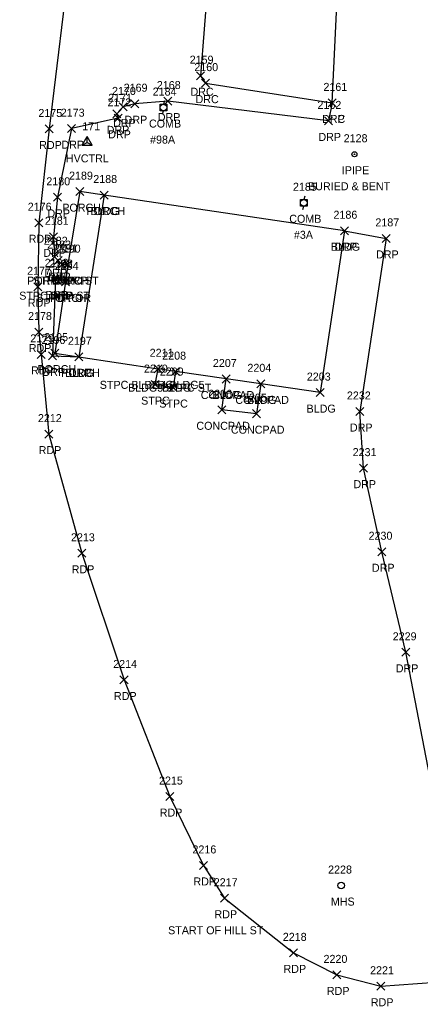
# Model space of a CAD drawing. Extents: x 1767353 to 1772625, y 740790 to 747702.
# Drawn here: x 1770037.8 to 1770137.8, y 741104.5 to 741351 of the extents above; entities that cross this region are included whole.
import ezdxf

# ---------------------------------------------------------------- set-up
doc = ezdxf.new("R2010")
doc.units = 0
for name, color, linetype in [('C_A', 7, 'Continuous'), ('C_I', 7, 'Continuous'), ('CPSM', 7, 'Continuous'), ('L_A', 7, 'Continuous'), ('L_I', 7, 'Continuous'), ('L_TIC', 7, 'Continuous'), ('LBC', 7, 'Continuous'), ('LBF', 7, 'Continuous'), ('LS', 7, 'Continuous'), ('M_A', 7, 'Continuous'), ('M_C', 7, 'Continuous'), ('M_I', 7, 'Continuous'), ('MPIP', 7, 'Continuous'), ('P_A', 7, 'Continuous'), ('P_C', 7, 'Continuous'), ('P_I', 7, 'Continuous'), ('P_TIC', 7, 'Continuous'), ('PET', 7, 'Continuous'), ('R_A', 7, 'Continuous'), ('R_I', 7, 'Continuous'), ('R_TIC', 7, 'Continuous'), ('RDP', 7, 'Continuous'), ('U_A', 7, 'Continuous'), ('U_C', 7, 'Continuous'), ('U_I', 7, 'Continuous'), ('UP', 7, 'Continuous'), ('USMH', 7, 'Continuous')]:
    doc.layers.add(name, color=color, linetype=linetype)

msp = doc.modelspace()

# ---------------------------------------------------------------- linework, layer by layer
at = {"layer": 'CPSM'}
for p, q in [((1770053.4, 741319.61), (1770054.65, 741321.77)), ((1770055.9, 741319.61), (1770054.65, 741321.77)), ((1770054.65, 741320.33), (1770054.65, 741321.77)), ((1770053.4, 741319.61), (1770054.65, 741320.33)), ((1770053.4, 741319.61), (1770055.9, 741319.61)), ((1770054.65, 741320.33), (1770054.65, 741320.33)), ((1770054.65, 741320.33), (1770055.9, 741319.61))]:
    msp.add_line(p, q, dxfattribs=at)
at = {"layer": 'L_TIC'}
for points in [[(1770051.83, 741307.02), (1770053.83, 741309.02)], [(1770053.83, 741307.02), (1770051.83, 741309.02)], [(1770057.87, 741306.17), (1770059.87, 741308.17)], [(1770059.87, 741306.17), (1770057.87, 741308.17)], [(1770057.87, 741306.17), (1770059.87, 741308.17)], [(1770059.87, 741306.17), (1770057.87, 741308.17)], [(1770117.9, 741297.25), (1770119.9, 741299.25)], [(1770119.9, 741297.25), (1770117.9, 741299.25)], [(1770117.9, 741297.25), (1770119.9, 741299.25)], [(1770119.9, 741297.25), (1770117.9, 741299.25)], [(1770047.43, 741288.82), (1770049.43, 741290.82)], [(1770049.43, 741288.82), (1770047.43, 741290.82)], [(1770048.84, 741288.78), (1770050.84, 741290.78)], [(1770050.84, 741288.78), (1770048.84, 741290.78)], [(1770048.84, 741288.78), (1770050.84, 741290.78)], [(1770050.84, 741288.78), (1770048.84, 741290.78)], [(1770046.83, 741285.03), (1770048.83, 741287.03)], [(1770048.83, 741285.03), (1770046.83, 741287.03)], [(1770048.26, 741284.47), (1770050.26, 741286.47)], [(1770050.26, 741284.47), (1770048.26, 741286.47)], [(1770048.26, 741284.47), (1770050.26, 741286.47)], [(1770050.26, 741284.47), (1770048.26, 741286.47)], [(1770045.62, 741266.69), (1770047.62, 741268.69)], [(1770047.62, 741266.69), (1770045.62, 741268.69)], [(1770051.54, 741265.76), (1770053.54, 741267.76)], [(1770053.54, 741265.76), (1770051.54, 741267.76)], [(1770051.54, 741265.76), (1770053.54, 741267.76)], [(1770053.54, 741265.76), (1770051.54, 741267.76)], [(1770071.38, 741262.76), (1770073.38, 741264.76)], [(1770073.38, 741262.76), (1770071.38, 741264.76)], [(1770071.38, 741262.76), (1770073.38, 741264.76)], [(1770073.38, 741262.76), (1770071.38, 741264.76)], [(1770071.38, 741262.76), (1770073.38, 741264.76)], [(1770073.38, 741262.76), (1770071.38, 741264.76)], [(1770075.74, 741262.06), (1770077.74, 741264.06)], [(1770077.74, 741262.06), (1770075.74, 741264.06)], [(1770075.74, 741262.06), (1770077.74, 741264.06)], [(1770077.74, 741262.06), (1770075.74, 741264.06)], [(1770088.38, 741260.22), (1770090.38, 741262.22)], [(1770090.38, 741260.22), (1770088.38, 741262.22)], [(1770088.38, 741260.22), (1770090.38, 741262.22)], [(1770090.38, 741260.22), (1770088.38, 741262.22)], [(1770070.61, 741258.82), (1770072.61, 741260.82)], [(1770072.61, 741258.82), (1770070.61, 741260.82)], [(1770075.15, 741258.08), (1770077.15, 741260.08)], [(1770077.15, 741258.08), (1770075.15, 741260.08)], [(1770097, 741259.01), (1770099, 741261.01)], [(1770099, 741259.01), (1770097, 741261.01)], [(1770097, 741259.01), (1770099, 741261.01)], [(1770099, 741259.01), (1770097, 741261.01)], [(1770111.84, 741256.82), (1770113.84, 741258.82)], [(1770113.84, 741256.82), (1770111.84, 741258.82)], [(1770087.27, 741252.53), (1770089.27, 741254.53)], [(1770089.27, 741252.53), (1770087.27, 741254.53)], [(1770095.9, 741251.56), (1770097.9, 741253.56)], [(1770097.9, 741251.56), (1770095.9, 741253.56)]]:
    msp.add_lwpolyline(points, dxfattribs=at)
at = {"layer": 'LBC'}
for points in [[(1770118.9, 741298.25), (1770058.87, 741307.17), (1770052.54, 741266.76), (1770072.38, 741263.76)], [(1770118.9, 741298.25), (1770112.84, 741257.82), (1770098, 741260.01), (1770089.38, 741261.22), (1770076.74, 741263.06), (1770072.38, 741263.76)]]:
    msp.add_lwpolyline(points, dxfattribs=at)
at = {"layer": 'LBF'}
for points in [[(1770058.87, 741307.17), (1770052.83, 741308.02), (1770049.84, 741289.78), (1770049.26, 741285.47), (1770046.62, 741267.69), (1770052.54, 741266.76)], [(1770049.84, 741289.78), (1770048.43, 741289.82), (1770047.83, 741286.03), (1770049.26, 741285.47)], [(1770076.74, 741263.06), (1770076.15, 741259.08), (1770071.61, 741259.82), (1770072.38, 741263.76)]]:
    msp.add_lwpolyline(points, dxfattribs=at)
at = {"layer": 'LS'}
msp.add_lwpolyline([(1770098, 741260.01), (1770096.9, 741252.56), (1770088.27, 741253.53), (1770089.38, 741261.22)], dxfattribs=at)
at = {"layer": 'MPIP'}
for radius in [0.625, 0.0833]:
    msp.add_circle((1770121.39, 741317.36), radius, dxfattribs=at)
at = {"layer": 'P_TIC'}
for points in [[(1770044.18, 741322.67), (1770046.18, 741324.67)], [(1770046.18, 741322.67), (1770044.18, 741324.67)], [(1770041.56, 741299.25), (1770043.56, 741301.25)], [(1770043.56, 741299.25), (1770041.56, 741301.25)], [(1770041.35, 741283.25), (1770043.35, 741285.25)], [(1770043.35, 741283.25), (1770041.35, 741285.25)], [(1770041.59, 741271.95), (1770043.59, 741273.95)], [(1770043.59, 741271.95), (1770041.59, 741273.95)], [(1770042.15, 741266.37), (1770044.15, 741268.37)], [(1770044.15, 741266.37), (1770042.15, 741268.37)], [(1770044.05, 741246.45), (1770046.05, 741248.45)], [(1770046.05, 741246.45), (1770044.05, 741248.45)], [(1770052.3, 741216.68), (1770054.3, 741218.68)], [(1770054.3, 741216.68), (1770052.3, 741218.68)], [(1770062.85, 741185.04), (1770064.85, 741187.04)], [(1770064.85, 741185.04), (1770062.85, 741187.04)], [(1770074.28, 741155.92), (1770076.28, 741157.92)], [(1770076.28, 741155.92), (1770074.28, 741157.92)], [(1770082.69, 741138.71), (1770084.69, 741140.71)], [(1770084.69, 741138.71), (1770082.69, 741140.71)], [(1770087.95, 741130.52), (1770089.95, 741132.52)], [(1770089.95, 741130.52), (1770087.95, 741132.52)], [(1770105.19, 741116.88), (1770107.19, 741118.88)], [(1770107.19, 741116.88), (1770105.19, 741118.88)], [(1770116.02, 741111.37), (1770118.02, 741113.37)], [(1770118.02, 741111.37), (1770116.02, 741113.37)], [(1770126.99, 741108.54), (1770128.99, 741110.54)], [(1770128.99, 741108.54), (1770126.99, 741110.54)]]:
    msp.add_lwpolyline(points, dxfattribs=at)
at = {"layer": 'PET'}
msp.add_lwpolyline([(1770050.58, 741368.28), (1770045.18, 741323.67), (1770042.56, 741300.25), (1770042.35, 741284.25), (1770042.59, 741272.95), (1770043.15, 741267.37), (1770045.05, 741247.45), (1770053.3, 741217.68), (1770063.85, 741186.04), (1770075.28, 741156.92), (1770083.69, 741139.71), (1770088.95, 741131.52), (1770106.19, 741117.88), (1770117.02, 741112.37), (1770127.99, 741109.54), (1770141.73, 741110.59)], dxfattribs=at)
at = {"layer": 'R_TIC'}
for points in [[(1770081.95, 741335.98), (1770083.95, 741337.98)], [(1770083.95, 741335.98), (1770081.95, 741337.98)], [(1770083.22, 741334.12), (1770085.22, 741336.12)], [(1770085.22, 741334.12), (1770083.22, 741336.12)], [(1770073.79, 741329.64), (1770075.79, 741331.64)], [(1770075.79, 741329.64), (1770073.79, 741331.64)], [(1770062.64, 741328.18), (1770064.64, 741330.18)], [(1770064.64, 741328.18), (1770062.64, 741330.18)], [(1770065.52, 741328.98), (1770067.52, 741330.98)], [(1770067.52, 741328.98), (1770065.52, 741330.98)], [(1770114.82, 741329.18), (1770116.82, 741331.18)], [(1770116.82, 741329.18), (1770114.82, 741331.18)], [(1770114.82, 741329.18), (1770116.82, 741331.18)], [(1770116.82, 741329.18), (1770114.82, 741331.18)], [(1770061.03, 741326.46), (1770063.03, 741328.46)], [(1770063.03, 741326.46), (1770061.03, 741328.46)], [(1770061.42, 741325.34), (1770063.42, 741327.34)], [(1770063.42, 741325.34), (1770061.42, 741327.34)], [(1770113.89, 741324.68), (1770115.89, 741326.68)], [(1770115.89, 741324.68), (1770113.89, 741326.68)], [(1770049.75, 741322.75), (1770051.75, 741324.75)], [(1770051.75, 741322.75), (1770049.75, 741324.75)], [(1770046.24, 741305.6), (1770048.24, 741307.6)], [(1770048.24, 741305.6), (1770046.24, 741307.6)], [(1770117.9, 741297.25), (1770119.9, 741299.25)], [(1770119.9, 741297.25), (1770117.9, 741299.25)], [(1770045.21, 741295.73), (1770047.21, 741297.73)], [(1770047.21, 741295.73), (1770045.21, 741297.73)], [(1770128.31, 741295.34), (1770130.31, 741297.34)], [(1770130.31, 741295.34), (1770128.31, 741297.34)], [(1770045.52, 741290.76), (1770047.52, 741292.76)], [(1770047.52, 741290.76), (1770045.52, 741292.76)], [(1770046.38, 741289.79), (1770048.38, 741291.79)], [(1770048.38, 741289.79), (1770046.38, 741291.79)], [(1770047.43, 741288.82), (1770049.43, 741290.82)], [(1770049.43, 741288.82), (1770047.43, 741290.82)], [(1770045.75, 741285.24), (1770047.75, 741287.24)], [(1770047.75, 741285.24), (1770045.75, 741287.24)], [(1770046.83, 741285.03), (1770048.83, 741287.03)], [(1770048.83, 741285.03), (1770046.83, 741287.03)], [(1770045.02, 741265.97), (1770047.02, 741267.97)], [(1770047.02, 741265.97), (1770045.02, 741267.97)], [(1770051.54, 741265.76), (1770053.54, 741267.76)], [(1770053.54, 741265.76), (1770051.54, 741267.76)], [(1770121.76, 741252.1), (1770123.76, 741254.1)], [(1770123.76, 741252.1), (1770121.76, 741254.1)], [(1770121.76, 741252.1), (1770123.76, 741254.1)], [(1770123.76, 741252.1), (1770121.76, 741254.1)], [(1770122.64, 741237.95), (1770124.64, 741239.95)], [(1770124.64, 741237.95), (1770122.64, 741239.95)], [(1770127.25, 741217.07), (1770129.25, 741219.07)], [(1770129.25, 741217.07), (1770127.25, 741219.07)], [(1770133.21, 741191.95), (1770135.21, 741193.95)], [(1770135.21, 741191.95), (1770133.21, 741193.95)]]:
    msp.add_lwpolyline(points, dxfattribs=at)
at = {"layer": 'RDP'}
for points in [[(1770093.41, 741409.44), (1770070.88, 741411.63), (1770069.4, 741411.52), (1770065.35, 741363.07), (1770066.76, 741361.57), (1770084.76, 741360.37), (1770082.95, 741336.98), (1770084.22, 741335.12), (1770115.82, 741330.18), (1770117.41, 741363.31)], [(1770115.82, 741330.18), (1770114.89, 741325.68), (1770074.79, 741330.64), (1770066.52, 741329.98), (1770063.64, 741329.18), (1770062.03, 741327.46), (1770062.42, 741326.34), (1770050.75, 741323.75), (1770047.24, 741306.6), (1770046.21, 741296.73), (1770046.52, 741291.76), (1770047.38, 741290.79), (1770048.43, 741289.82)], [(1770118.9, 741298.25), (1770129.31, 741296.34), (1770122.76, 741253.1)], [(1770047.83, 741286.03), (1770046.75, 741286.24), (1770046.02, 741266.97), (1770052.54, 741266.76)], [(1770155.4, 741112.86), (1770152.93, 741117.01), (1770146.3, 741135.52), (1770141.6, 741154.57), (1770134.21, 741192.95), (1770128.25, 741218.07), (1770123.64, 741238.95), (1770122.76, 741253.1)]]:
    msp.add_lwpolyline(points, dxfattribs=at)
at = {"layer": 'UP'}
for p, q in [((1770072.87, 741328.19), (1770072.87, 741329.86)), ((1770072.87, 741329.86), (1770074.54, 741329.86)), ((1770073.96, 741330.69), (1770073.71, 741329.86)), ((1770073.71, 741329.02), (1770073.71, 741329.02)), ((1770074.54, 741329.86), (1770074.54, 741328.19)), ((1770074.54, 741328.19), (1770072.87, 741328.19)), ((1770073.46, 741327.36), (1770073.71, 741328.19)), ((1770108.97, 741306.91), (1770108.72, 741306.07)), ((1770107.89, 741304.41), (1770107.89, 741306.07)), ((1770107.89, 741306.07), (1770109.55, 741306.07)), ((1770109.55, 741304.41), (1770107.89, 741304.41)), ((1770108.47, 741303.57), (1770108.72, 741304.41)), ((1770108.72, 741305.24), (1770108.72, 741305.24)), ((1770109.55, 741306.07), (1770109.55, 741304.41))]:
    msp.add_line(p, q, dxfattribs=at)
for centre in [(1770073.71, 741329.02), (1770108.72, 741305.24)]:
    msp.add_circle(centre, 0.833, dxfattribs=at)
at = {"layer": 'USMH'}
for p, q in [((1770118.07, 741134.69), (1770118.07, 741134.69)), ((1770118.9, 741134.69), (1770118.9, 741134.69))]:
    msp.add_line(p, q, dxfattribs=at)
msp.add_circle((1770118.07, 741134.69), 0.833, dxfattribs=at)

# ---------------------------------------------------------------- texts
at = {"layer": 'C_A'}
msp.add_text('HVCTRL', height=2, dxfattribs=at).set_placement((1770049.35, 741315.33))
at = {"layer": 'C_I'}
msp.add_text('171', height=2, dxfattribs=at).set_placement((1770053.43, 741323.33))
at = {"layer": 'L_A'}
for s, p in [('PORCH', (1770048.45, 741303.02)), ('PORCH', (1770054.5, 741302.17)), ('BLDG', (1770055.46, 741302.17)), ('BLDG', (1770115.49, 741293.25)), ('BLDG', (1770115.49, 741293.25)), ('STPC DRP', (1770041.16, 741284.82)), ('POR STPC ST', (1770039.68, 741284.78)), ('PORCH', (1770045.47, 741284.78)), ('STPC DRP ST', (1770037.7, 741281.03)), ('STPC POR', (1770041.96, 741280.47)), ('PORCH', (1770044.88, 741280.47)), ('PORCH', (1770042.24, 741262.69)), ('PORCH', (1770048.16, 741261.76)), ('BLDG', (1770049.13, 741261.76)), ('STPC BLDG4 BLDG5', (1770057.8, 741258.76)), ('BLDG5 STPC ST', (1770064.86, 741258.06)), ('BLDG', (1770068.97, 741258.76)), ('BLDG', (1770068.97, 741258.76)), ('BLDG', (1770073.33, 741258.06)), ('CONCPAD', (1770083.02, 741256.22)), ('BLDG', (1770085.97, 741256.22)), ('STPC', (1770068.13, 741254.82)), ('STPC', (1770072.66, 741254.08)), ('CONCPAD', (1770091.64, 741255.01)), ('BLDG', (1770094.59, 741255.01)), ('BLDG', (1770109.43, 741252.82)), ('CONCPAD', (1770081.92, 741248.53)), ('CONCPAD', (1770090.54, 741247.56))]:
    msp.add_text(s, height=2, dxfattribs=at).set_placement(p)
at = {"layer": 'L_I'}
for s, p in [('2189', (1770050.13, 741311.02)), ('2188', (1770056.18, 741310.17)), ('2188', (1770056.18, 741310.17)), ('2186', (1770116.15, 741301.25)), ('2186', (1770116.15, 741301.25)), ('2191', (1770046.3, 741292.82)), ('2190', (1770047.07, 741292.78)), ('2190', (1770047.07, 741292.78)), ('2192', (1770045.14, 741289.03)), ('2194', (1770046.56, 741288.47)), ('2194', (1770046.56, 741288.47)), ('2195', (1770043.93, 741270.69)), ('2197', (1770049.85, 741269.76)), ('2197', (1770049.85, 741269.76)), ('2211', (1770070.26, 741266.76)), ('2211', (1770070.26, 741266.76)), ('2211', (1770070.26, 741266.76)), ('2208', (1770073.4, 741266.06)), ('2208', (1770073.4, 741266.06)), ('2210', (1770068.83, 741262.82)), ('2207', (1770086.04, 741264.22)), ('2207', (1770086.04, 741264.22)), ('2204', (1770094.66, 741263.01)), ('2204', (1770094.66, 741263.01)), ('2209', (1770072.8, 741262.08)), ('2203', (1770109.5, 741260.82)), ('2206', (1770084.88, 741256.53)), ('2205', (1770093.56, 741255.56))]:
    msp.add_text(s, height=2, dxfattribs=at).set_placement(p)
at = {"layer": 'M_A'}
msp.add_text('IPIPE', height=2, dxfattribs=at).set_placement((1770118.23, 741312.36))
at = {"layer": 'M_C'}
msp.add_text('BURIED & BENT', height=2, dxfattribs=at).set_placement((1770109.81, 741308.36))
at = {"layer": 'M_I'}
msp.add_text('2128', height=2, dxfattribs=at).set_placement((1770118.7, 741320.36))
at = {"layer": 'P_A'}
for p in [(1770042.67, 741318.67), (1770040.05, 741295.25), (1770039.84, 741279.25), (1770040.08, 741267.95), (1770040.64, 741262.37), (1770042.54, 741242.45), (1770050.79, 741212.68), (1770061.34, 741181.04), (1770072.77, 741151.92), (1770081.18, 741134.71), (1770086.44, 741126.52), (1770103.68, 741112.88), (1770114.5, 741107.37), (1770125.48, 741104.54)]:
    msp.add_text('RDP', height=2, dxfattribs=at).set_placement(p)
at = {"layer": 'P_C'}
msp.add_text('START OF HILL ST', height=2, dxfattribs=at).set_placement((1770074.86, 741122.52))
at = {"layer": 'P_I'}
for s, p in [('2175', (1770042.48, 741326.67)), ('2176', (1770039.82, 741303.25)), ('2177', (1770039.66, 741287.25)), ('2178', (1770039.9, 741275.95)), ('2179', (1770040.45, 741270.37)), ('2212', (1770042.36, 741250.45)), ('2213', (1770050.61, 741220.68)), ('2214', (1770061.16, 741189.04)), ('2215', (1770072.59, 741159.92)), ('2216', (1770080.94, 741142.71)), ('2217', (1770086.26, 741134.52)), ('2218', (1770103.5, 741120.88)), ('2220', (1770113.67, 741115.37)), ('2221', (1770125.29, 741112.54))]:
    msp.add_text(s, height=2, dxfattribs=at).set_placement(p)
at = {"layer": 'R_A'}
for s, p in [('DRC', (1770080.44, 741331.98)), ('DRC', (1770081.71, 741330.12)), ('DRP', (1770064, 741324.98)), ('DRP', (1770072.28, 741325.64)), ('DRC', (1770113.31, 741325.18)), ('DRP', (1770113.31, 741325.18)), ('DRP', (1770059.52, 741322.46)), ('DRP', (1770061.13, 741324.18)), ('DRP', (1770059.91, 741321.34)), ('DRP', (1770112.38, 741320.68)), ('DRP', (1770048.24, 741318.75)), ('DRP', (1770044.73, 741301.6)), ('DRP', (1770116.39, 741293.25)), ('DRP', (1770043.7, 741291.73)), ('DRP', (1770126.79, 741291.34)), ('DRP', (1770044.01, 741286.76)), ('DRP', (1770044.87, 741285.79)), ('DRP', (1770045.92, 741284.82)), ('DRP', (1770044.23, 741281.24)), ('DRP', (1770045.32, 741281.03)), ('DRP', (1770043.5, 741261.97)), ('DRP', (1770050.03, 741261.76)), ('DRP', (1770120.25, 741248.1)), ('DRP', (1770120.25, 741248.1)), ('DRP', (1770121.13, 741233.95)), ('DRP', (1770125.74, 741213.07)), ('DRP', (1770131.7, 741187.95))]:
    msp.add_text(s, height=2, dxfattribs=at).set_placement(p)
at = {"layer": 'R_I'}
for s, p in [('2159', (1770080.25, 741339.98)), ('2160', (1770081.4, 741338.12)), ('2170', (1770060.86, 741332.18)), ('2169', (1770063.77, 741332.98)), ('2168', (1770072.05, 741333.64)), ('2161', (1770113.64, 741333.18)), ('2161', (1770113.64, 741333.18)), ('2172', (1770059.73, 741329.34)), ('2171', (1770059.9, 741330.46)), ('2173', (1770048.06, 741326.75)), ('2162', (1770112.15, 741328.68)), ('2180', (1770044.46, 741309.6)), ('2181', (1770044.09, 741299.73)), ('2186', (1770116.15, 741301.25)), ('2187', (1770126.61, 741299.34)), ('2182', (1770043.83, 741294.76)), ('2183', (1770044.69, 741293.79)), ('2191', (1770046.3, 741292.82)), ('2193', (1770044.05, 741289.24)), ('2192', (1770045.14, 741289.03)), ('2196', (1770043.27, 741269.97)), ('2197', (1770049.85, 741269.76)), ('2232', (1770119.5, 741256.1)), ('2232', (1770119.5, 741256.1)), ('2231', (1770120.94, 741241.95)), ('2230', (1770124.91, 741221.07)), ('2229', (1770130.94, 741195.95))]:
    msp.add_text(s, height=2, dxfattribs=at).set_placement(p)
at = {"layer": 'U_A'}
for s, p in [('COMB', (1770070.09, 741324.02)), ('COMB', (1770105.11, 741300.24)), ('MHS', (1770115.49, 741129.69))]:
    msp.add_text(s, height=2, dxfattribs=at).set_placement(p)
at = {"layer": 'U_C'}
for s, p in [('#98A', (1770070.36, 741320.02)), ('#3A', (1770106.27, 741296.24))]:
    msp.add_text(s, height=2, dxfattribs=at).set_placement(p)
at = {"layer": 'U_I'}
for s, p in [('2184', (1770071.01, 741332.02)), ('2185', (1770106.03, 741308.24)), ('2228', (1770114.81, 741137.69))]:
    msp.add_text(s, height=2, dxfattribs=at).set_placement(p)

doc.saveas('drawing.dxf')
